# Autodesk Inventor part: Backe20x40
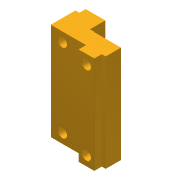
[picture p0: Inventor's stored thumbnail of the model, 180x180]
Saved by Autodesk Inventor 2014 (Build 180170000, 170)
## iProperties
Created: 2014-03
Part Number: Backe20x40
Material: Generisch
Document SubType Name: Modeling
Designer: e_dammj
Density: 1 g/cm^3
Appearance: Vorgabe
Sending System: SolidWorks 2011
Last Author: e_boekem
Author: e_dammj
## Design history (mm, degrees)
node "Backe20x40.ipt1"
node "Aufsatz-Linear austragen5"
node "Basis1"
